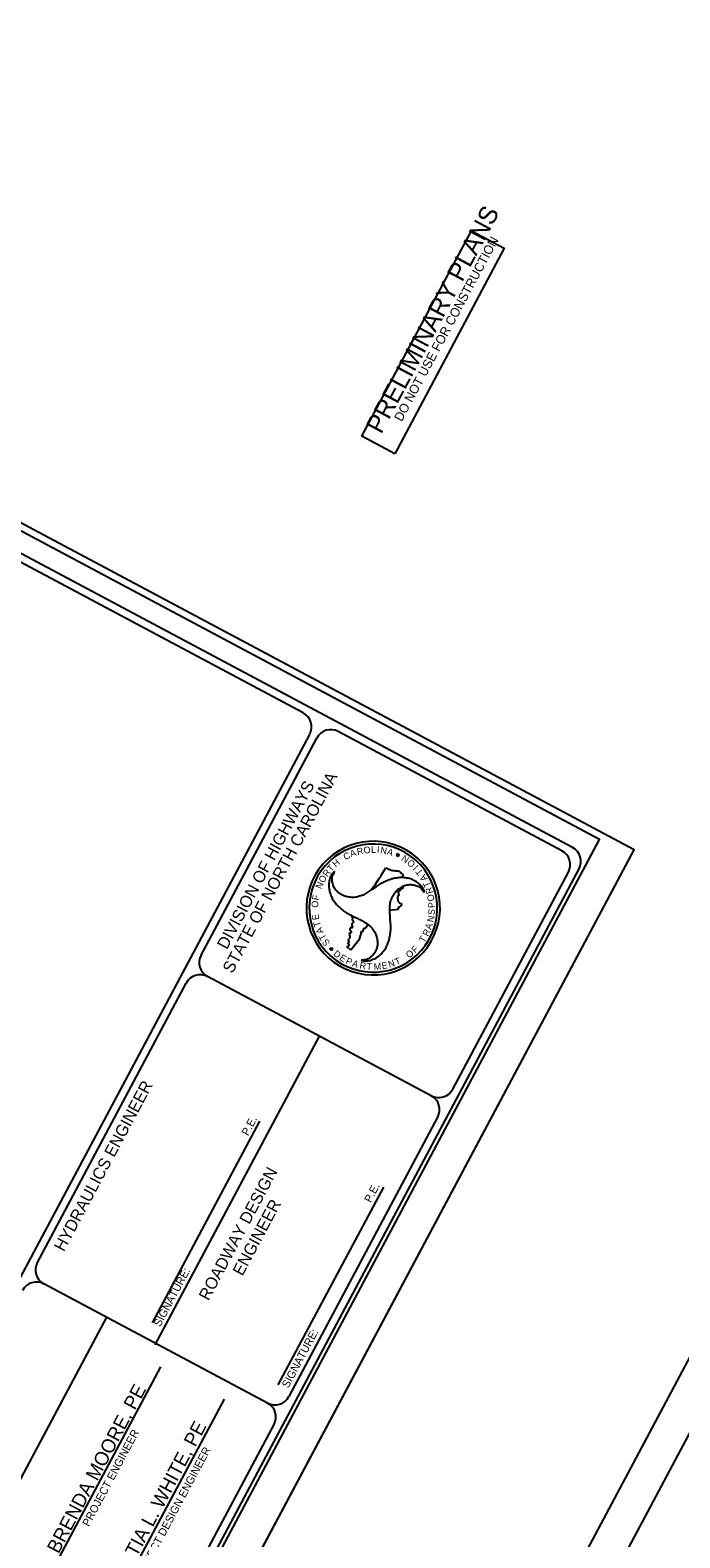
# Model space of a CAD drawing. Extents: x 1970823 to 1988115, y 770601 to 786368.
# Drawn here: x 1979112 to 1981572, y 780658 to 786368 of the extents above; entities that cross this region are included whole.
import ezdxf

# ---------------------------------------------------------------- set-up
doc = ezdxf.new("R2010")
doc.units = 0
for name, color, linetype in [('Old_Level_50', 7, 'Continuous'), ('Old_Level_51', 7, 'Continuous'), ('Sheet Cutting Line CELL', 7, 'Continuous'), ('Sheet Data Field CELL', 7, 'Continuous'), ('Sheet Plot Border Inside CELL', 7, 'Continuous'), ('Sheet Plot Border Outside CELL', 7, 'Continuous'), ('Sheet Sticker Preliminary CELL', 7, 'Continuous'), ('Sheet Title CELL', 7, 'Continuous')]:
    doc.layers.add(name, color=color, linetype=linetype)

msp = doc.modelspace()

# ---------------------------------------------------------------- linework, layer by layer
at = {"layer": 'Old_Level_50'}
for points in [[(1975680.9, 786280.6), (1970978.5, 777456.3), (1976565.4, 774479.1), (1981267.8, 783303.4)], [(1982396.2, 782534.2), (1977693.8, 773709.9), (1983280.6, 770732.7), (1987983, 779557)]]:
    msp.add_lwpolyline(points, close=True, dxfattribs=at)
at = {"layer": 'Old_Level_51'}
for points in [[(1975574.8, 786367.7), (1970823, 777450.8), (1976647.6, 774346.9), (1981399.3, 783263.8)], [(1982290, 782621.4), (1977538.2, 773704.4), (1983362.8, 770600.5), (1988114.6, 779517.5)]]:
    msp.add_lwpolyline(points, close=True, dxfattribs=at)
at = {"layer": 'Sheet Cutting Line CELL'}
msp.add_line((1976647.6, 774346.9), (1981399.3, 783263.8), dxfattribs=at)
at = {"layer": 'Sheet Plot Border Inside CELL'}
msp.add_lwpolyline([(1976565.4, 774479.1), (1981267.8, 783303.3), (1975681, 786280.5), (1970978.6, 777456.3)], close=True, dxfattribs=at)
at = {"layer": 'Sheet Plot Border Outside CELL'}
msp.add_lwpolyline([(1975574.8, 786367.7), (1970823, 777450.8), (1976647.6, 774346.9), (1981399.3, 783263.8)], close=True, dxfattribs=at)
at = {"layer": 'Sheet Sticker Preliminary CELL'}
msp.add_lwpolyline([(1980492.4, 784763.7), (1980368, 784830), (1980782.8, 785608.4), (1980907.2, 785542.1)], close=True, dxfattribs=at)
at = {"layer": 'Sheet Title CELL'}
for p, q in [((1976163.8, 776182), (1980170.6, 783701.1)), ((1979759.1, 782865), (1980197.1, 783687)), ((1980502.2, 783243.8), (1980499.6, 783240.3)), ((1980499.6, 783240.3), (1980503.8, 783241.7)), ((1980503.8, 783246.1), (1980499.7, 783247.3)), ((1980499.7, 783247.3), (1980502.2, 783243.8)), ((1980506.2, 783249.7), (1980503.8, 783246.1)), ((1980503.8, 783241.7), (1980506.5, 783238.2)), ((1980506.3, 783245.3), (1980506.2, 783249.7)), ((1980510.5, 783243.8), (1980506.3, 783245.3)), ((1980506.4, 783242.5), (1980510.5, 783243.8)), ((1980506.5, 783238.2), (1980506.4, 783242.5)), ((1980558.3, 783248.8), (1980558.3, 783248.8)), ((1980263.7, 783181.7), (1980263.8, 783181)), ((1980263.7, 783181.7), (1980263.8, 783181)), ((1980405.8, 783113.2), (1980405.8, 783113.2)), ((1980505, 783037.6), (1980473.9, 783033.8)), ((1980473.9, 783033.8), (1980473.9, 783033.8)), ((1980392, 782980.9), (1980380.2, 782964.7)), ((1980355.9, 782922.3), (1980326.4, 782884.3)), ((1980365.3, 782949.4), (1980355.9, 782922.3)), ((1980249.4, 782888.7), (1980246.8, 782892)), ((1980246.8, 782892), (1980251, 782890.9)), ((1980246.8, 782885.1), (1980249.4, 782888.7)), ((1980251, 782886.4), (1980246.8, 782885.1)), ((1980251, 782890.9), (1980253.5, 782894.4)), ((1980253.7, 782883), (1980251, 782886.4)), ((1980253.5, 782894.4), (1980253.5, 782890)), ((1980253.5, 782890), (1980257.7, 782888.6)), ((1980257.7, 782888.6), (1980253.5, 782887.2)), ((1980253.5, 782887.2), (1980253.7, 782883)), ((1980326.4, 782884.3), (1980314.4, 782893.6)), ((1979138.9, 781701.3), (1979702.6, 782759.1)), ((1980631, 782332.4), (1979783.8, 782783.8)), ((1979584.6, 781389.7), (1980207.3, 782558.2)), ((1979574.5, 781472.6), (1979981.5, 782236.4)), ((1980051.2, 781237.3), (1980450.5, 781986.5)), ((1980011, 781168.6), (1979163.7, 781620.1)), ((1979400.7, 781493.8), (1978540, 779878.9)), ((1979168.9, 780485), (1979606.8, 781306.5)), ((1979406.2, 780356.2), (1979847.1, 781183.5))]:
    msp.add_line(p, q, dxfattribs=at)
for points in [[(1981166, 783272.6), (1975712.2, 786178.9)], [(1980145.9, 783782.2), (1975724.5, 786138.4)], [(1981125.5, 783260.2), (1980278.3, 783711.7)], [(1977014.7, 775354.7), (1981190.8, 783191.4)], [(1980712.2, 782357.1), (1981150.2, 783179)], [(1980092.1, 781193.4), (1980655.8, 782251.2)], [(1979231.4, 779578.4), (1980035.7, 781087.5)]]:
    msp.add_lwpolyline(points, dxfattribs=at)
for centre, radius, start, end in [((1980117.4, 783729.4), 60, 331.9471, 61.9471), ((1980249.8, 783658.9), 60, 61.9471, 151.9471), ((1980411, 783043.1), 253, 54.3682, 234.3682), ((1980411, 783043.1), 242.5, 54.3682, 234.3682), ((1981137.6, 783219.8), 60, 331.9471, 61.9471), ((1980411, 783043.1), 253, 234.3682, 54.3682), ((1980411, 783043.1), 242.5, 234.3682, 54.3682), ((1981097, 783207.4), 60, 331.9471, 61.9471), ((1979306.4, 783869.1), 1334.1, 325.4858, 329.6918), ((1979306.4, 783869.1), 1334.1, 320.0467, 320.1463), ((1979812, 782836.8), 60, 151.9471, 241.9471), ((1979755.6, 782730.9), 60, 61.9471, 151.9471), ((1980658.9, 782385.5), 60, 241.9471, 331.9471), ((1980602.5, 782279.6), 60, 331.9471, 61.9471), ((1979191.7, 781673.2), 60, 151.9471, 241.9471), ((1979135.2, 781567.3), 60, 61.9471, 151.9471), ((1980038.9, 781221.8), 60, 241.9471, 331.9471), ((1979982.4, 781115.9), 60, 331.9471, 61.9471)]:
    msp.add_arc(centre, radius, start, end, dxfattribs=at)
for points in [[(1980263.8, 783181), (1980259.3, 783177.3), (1980250.1, 783163.2), (1980244.5, 783146.1), (1980244.3, 783144.4), (1980243, 783134.8), (1980243.2, 783123.5), (1980245.8, 783104.8), (1980252.6, 783087), (1980255.7, 783079.6), (1980260.8, 783072.2), (1980272, 783057.2), (1980284.3, 783044.8), (1980300.1, 783032.1), (1980314.6, 783022.1), (1980331, 783013.9), (1980347.7, 783005.9), (1980363.6, 782997.7), (1980379.8, 782989.1), (1980394.6, 782978.6), (1980395.8, 782977.6), (1980409.6, 782963.8), (1980418.8, 782947.6), (1980424.4, 782931.2), (1980426.3, 782922.6), (1980426.7, 782911.8), (1980427, 782905.7), (1980425.1, 782893), (1980418.3, 782876.5), (1980407.6, 782863.3), (1980395.8, 782853.3), (1980381.2, 782847.6), (1980365.3, 782846.2)], [(1980604.5, 783101.6), (1980603.5, 783107.1), (1980596, 783122.3), (1980584, 783135.6), (1980582.7, 783136.8), (1980574.9, 783142.6), (1980565, 783148.1), (1980547.6, 783155.4), (1980528.7, 783158.2), (1980520.8, 783159.3), (1980511.7, 783158.6), (1980493.2, 783156.4), (1980476.3, 783152), (1980457.5, 783144.6), (1980441.6, 783136.9), (1980426.1, 783126.9), (1980410.9, 783116.5), (1980396, 783106.9), (1980380.2, 783097), (1980363.9, 783089.5), (1980362.4, 783089.1), (1980343.3, 783083.9), (1980324.8, 783084.1), (1980307.7, 783087.3), (1980299.6, 783090.2), (1980290, 783095.2), (1980284.3, 783097.9), (1980274.5, 783106), (1980263.5, 783120.2), (1980257.5, 783135.8), (1980254.9, 783151.1), (1980257.2, 783166.7), (1980263.8, 783181), (1980263.7, 783181.7)], [(1980517.5, 783159.4), (1980511.7, 783158.6), (1980493.2, 783156.4), (1980476.3, 783152), (1980457.5, 783144.6), (1980441.6, 783136.9), (1980426.1, 783126.9), (1980410.9, 783116.5), (1980405.8, 783113.2)], [(1980458.2, 783195.8), (1980474, 783188.9), (1980495.4, 783184.5), (1980507.5, 783182.8), (1980515, 783177.2), (1980522.9, 783168.9), (1980517.5, 783159.5)], [(1980365.3, 782846.2), (1980370.9, 782844.3), (1980387.7, 782843.3), (1980405.3, 782846.9), (1980406.7, 782847.6), (1980415.9, 782851.3), (1980425.5, 782857.2), (1980440.5, 782868.7), (1980452.3, 782883.5), (1980457.3, 782889.8), (1980461.3, 782898.3), (1980468.4, 782915.2), (1980473.1, 782931.9), (1980476.2, 782952), (1980477.6, 782969.5), (1980476.5, 782988), (1980475, 783006.4), (1980474.3, 783024.3), (1980473.7, 783042.7), (1980475.3, 783060.7), (1980475.7, 783062.5), (1980480.8, 783081.3), (1980490.1, 783097.2), (1980501.3, 783110.2), (1980508, 783116.4), (1980517.1, 783121.7), (1980522.3, 783125.5), (1980534.2, 783129.9), (1980551.8, 783132.2), (1980568.5, 783129.7), (1980583.2, 783124.3), (1980595.5, 783114.6), (1980604.5, 783101.6)], [(1980473.9, 783033.8), (1980473.7, 783042.7), (1980475.3, 783060.7), (1980475.7, 783062.5), (1980480.8, 783081.3), (1980490.1, 783097.2), (1980501.3, 783110.2), (1980508, 783116.4), (1980517.1, 783121.7), (1980522, 783125.2)], [(1980522, 783125.1), (1980524.2, 783120.6), (1980522.2, 783117.3), (1980514, 783115), (1980510.6, 783107.4), (1980506.6, 783105.6), (1980505.1, 783103.6), (1980507.7, 783094.5), (1980504.5, 783086.9), (1980504.7, 783070.6), (1980507.7, 783065.1), (1980518.1, 783058.8), (1980518.2, 783054.8), (1980515.4, 783052), (1980508.2, 783047.2), (1980505, 783037.6)], [(1980314.4, 782893.6), (1980312.9, 782894), (1980313.1, 782897.1), (1980319.6, 782901.1), (1980319.2, 782905.9), (1980316.6, 782907.5), (1980315.8, 782911.6), (1980319.4, 782915), (1980317.4, 782921.9), (1980319, 782925.8), (1980323.9, 782932.7), (1980321.5, 782946.9), (1980323.5, 782950.7), (1980326.4, 782950), (1980328.3, 782951.8), (1980324, 782960.2), (1980323.7, 782961.9), (1980325.8, 782970.2), (1980328.2, 782971), (1980331.6, 782969.3), (1980332.9, 782969.8), (1980332.9, 782973), (1980331.3, 782978.5), (1980332.3, 782985.7), (1980337.4, 782991.3), (1980333.2, 782995.8), (1980333.5, 783006.3), (1980331.7, 783009.8), (1980329, 783012.3)], [(1980330.6, 783014.1), (1980331, 783013.9), (1980347.7, 783005.9), (1980363.6, 782997.7), (1980379.8, 782989.1), (1980392, 782980.8)], [(1980380.2, 782964.7), (1980376.1, 782965.3), (1980372.9, 782962.8), (1980372.1, 782956.9), (1980369.6, 782953.8), (1980364.5, 782952.1), (1980365.3, 782949.4)]]:
    msp.add_spline(points, degree=3, dxfattribs=at)

# ---------------------------------------------------------------- texts
at = {"layer": 'Sheet Data Field CELL'}
for s, p in [('BRENDA MOORE, PE', (1979218.9, 780595.2)), ('TATIA L. WHITE, PE', (1979472.9, 780503.7))]:
    msp.add_text(s, height=52.501, rotation=61.9471, dxfattribs=at).set_placement(p)
at = {"layer": 'Sheet Sticker Preliminary CELL'}
for s, height, p in [('PRELIMINARY PLANS', 69.12, (1980441.1, 784835.2)), ('DO NOT USE FOR CONSTRUCTION', 34.56, (1980518.9, 784882.9))]:
    msp.add_text(s, height=height, rotation=61.9471, dxfattribs=at).set_placement(p)
at = {"layer": 'Sheet Title CELL'}
for s, height, rotation, p in [('STATE OF NORTH CAROLINA', 44.996, 61.9471, (1979877.6, 782793)), ('DIVISION OF HIGHWAYS', 44.996, 61.9471, (1979856.7, 782883.7)), ('A', 25.2, 19.6702, (1980327.9, 783235.1)), ('R', 25.2, 13.3063, (1980352.2, 783243.8)), ('O', 25.3, 6.1867, (1980375.7, 783249.3)), ('L', 25.2, 359.953, (1980402.4, 783252.2)), ('I', 25.3, 355.9637, (1980424.2, 783251.7)), ('N', 25.2, 350.2636, (1980436.5, 783250.7)), ('A', 25.2, 342.8316, (1980460.9, 783246.3)), ('T', 25.3, 46.5943, (1980251.6, 783178.6)), ('H', 25.2, 39.5096, (1980268.7, 783196.4)), ('C', 25.2, 27.1673, (1980305.4, 783223.7)), ('N', 25.2, 146.5764, (1980549.3, 783232.6)), ('O', 25.1, 139.3283, (1980572.6, 783213)), ('I', 25.3, 134.1927, (1980584, 783201.5)), ('O', 25.3, 59.8539, (1980223.8, 783136.2)), ('R', 25.2, 53.244, (1980237.2, 783159.2)), ('T', 25.2, 128.5428, (1980601.9, 783179.3)), ('A', 25.3, 121.4584, (1980617.8, 783153.9)), ('F', 25.3, 79.4389, (1980203.8, 783070.8)), ('N', 25.2, 67.352, (1980214.1, 783113.5)), ('T', 25.1, 113.3713, (1980629.6, 783127.9)), ('R', 25.3, 107.2716, (1980638.2, 783101.3)), ('O', 25.3, 100.0824, (1980643.7, 783071.3)), ('O', 25.3, 86.5858, (1980202, 783044.2)), ('S', 25.1, 86.1986, (1980643.8, 783016.5)), ('P', 25.2, 93.3905, (1980645.5, 783044.4)), ('E', 25.1, 98.5252, (1980206.5, 782999.7)), ('T', 25.2, 105.6408, (1980213, 782975.8)), ('A', 25.2, 71.9565, (1980630.1, 782959.9)), ('N', 25.2, 78.9881, (1980638.9, 782988.4)), ('A', 25.3, 112.696, (1980223.1, 782951.8)), ('T', 25.3, 119.7483, (1980235, 782930.2)), ('S', 25.2, 126.1245, (1980249.1, 782910.7)), ('T', 25.1, 58.2468, (1980604, 782910)), ('R', 25.2, 65.2034, (1980618.8, 782934.4)), ('D', 25.2, 322.2212, (1980257.6, 782865.9)), ('E', 25.1, 328.5091, (1980280.7, 782848.4)), ('O', 25.2, 38.1723, (1980546.5, 782851.8)), ('F', 25.2, 45.3375, (1980570.2, 782871)), ('P', 25.2, 336.0415, (1980304.3, 782834.5)), ('A', 25.2, 342.6341, (1980328.9, 782823.6)), ('R', 25.2, 349.7027, (1980357.6, 782815)), ('T', 25.2, 356.3532, (1980385, 782810.2)), ('M', 25.2, 3.5883, (1980413.6, 782808.8)), ('E', 25.2, 11.0551, (1980445.6, 782811.4)), ('N', 25.3, 18.0266, (1980472.3, 782816.9)), ('T', 25.2, 24.8686, (1980499.3, 782826)), (' HYDRAULICS ENGINEER', 45, 61.9471, (1979231.4, 781724.8)), ('P.E.', 30, 61.9471, (1979936.9, 782178.8)), ('ROADWAY DESIGN', 44.996, 61.9471, (1979787.4, 781553.6)), ('P.E.', 30, 61.9471, (1980401.5, 781925.2)), ('ENGINEER', 45, 61.9471, (1979915.6, 781647.4)), ('SIGNATURE:', 30, 61.9471, (1979603.8, 781455.1)), ('SIGNATURE:', 30, 61.9471, (1980089.2, 781223.1)), ('PROJECT ENGINEER', 29.997, 61.9471, (1979333.8, 780698.7)), ('PROJECT DESIGN ENGINEER', 29.997, 61.9471, (1979527.3, 780486.8))]:
    msp.add_text(s, height=height, rotation=rotation, dxfattribs=at).set_placement(p)

doc.saveas('drawing.dxf')
